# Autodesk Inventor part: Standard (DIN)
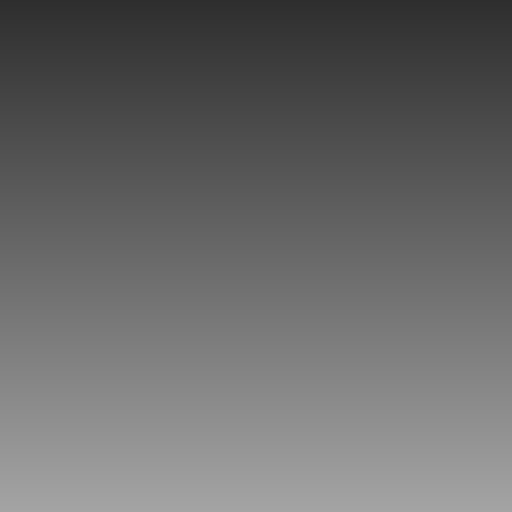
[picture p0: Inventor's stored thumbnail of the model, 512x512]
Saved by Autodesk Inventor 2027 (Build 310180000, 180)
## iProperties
Shininess: 64.0
Length Units: 11269
Angle Units: 11279
Time Units: 11290
Mass Units: 11283
Length Display Precision: 3
Angle Display Precision: 2
Compacted: True
Part Number: Standard (DIN)
Document SubType Name: Modeling
Created: 2002-07
Density: 1 g/cm^3
Material: Generic
Appearance: Default
Density: 0.0
Volumn: 0.0
Area: 0.0
PropertySet Name: Model Information
Control State: 0
Master: False
Checked Out: False
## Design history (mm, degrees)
